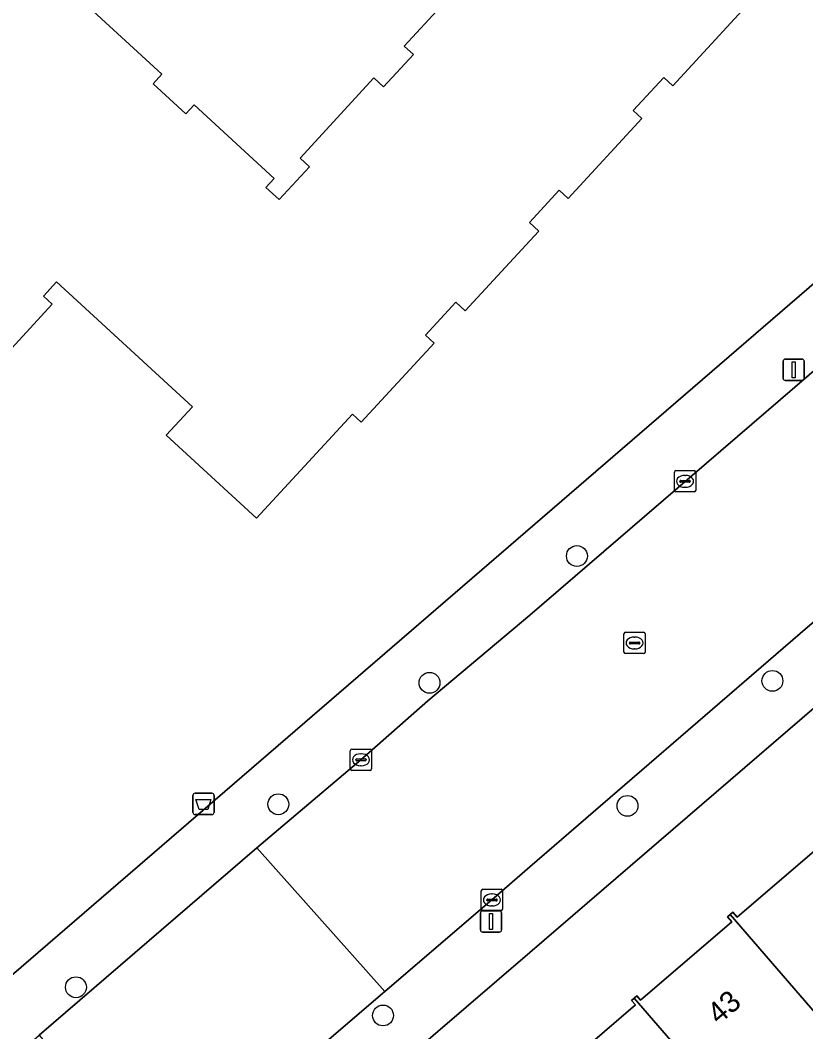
# Model space of a CAD drawing. Extents: x 159217 to 160349, y 381246 to 382172.
# Drawn here: x 159976.13 to 160012.93, y 381881.22 to 381928.65 of the extents above; entities that cross this region are included whole.
import ezdxf

# ---------------------------------------------------------------- set-up
doc = ezdxf.new("R2010")
doc.units = 0
for name, color, linetype in [('IMGEO_Afvalbak', 7, 'Continuous'), ('IMGEO_Boom', 7, 'Continuous'), ('IMGEO_Erf', 7, 'Continuous'), ('IMGEO_Kolk', 7, 'Continuous'), ('IMGEO_Lichtmast', 7, 'Continuous'), ('IMGEO_Pand', 7, 'Continuous'), ('IMGEO_Pand_nummerreeks', 7, 'Continuous'), ('IMGEO_Rijbaan_lokaal_open', 7, 'Continuous'), ('IMGEO_Rioolput', 7, 'Continuous'), ('IMGEO_Voetpad_open', 7, 'Continuous')]:
    doc.layers.add(name, color=color, linetype=linetype)

msp = doc.modelspace()

# ---------------------------------------------------------------- linework, layer by layer
at = {"layer": 'IMGEO_Afvalbak'}
for p, q in [((159984.22, 381891.506), (159984.22, 381892.306)), ((159984.22, 381892.306), (159984.22, 381891.506)), ((159984.32, 381892.406), (159985.11, 381892.406)), ((159985.11, 381892.406), (159984.32, 381892.406)), ((159985.21, 381892.306), (159985.21, 381891.506)), ((159985.21, 381891.506), (159985.21, 381892.306)), ((159985.11, 381891.406), (159984.32, 381891.406)), ((159984.32, 381891.406), (159985.11, 381891.406))]:
    msp.add_line(p, q, dxfattribs=at)
msp.add_lwpolyline([(159984.363, 381892.12), (159985.067, 381892.12), (159984.918, 381891.65), (159984.512, 381891.65), (159984.363, 381892.12)], dxfattribs=at)
for centre, start, end in [((159984.32, 381892.306), 90, 180), ((159984.32, 381892.306), 90, 180), ((159985.11, 381892.306), 0, 90), ((159985.11, 381892.306), 360, 90), ((159984.32, 381891.506), 180, 270), ((159984.32, 381891.506), 180, 270), ((159985.11, 381891.506), 270, 0), ((159985.11, 381891.506), 270, 0)]:
    msp.add_arc(centre, 0.1, start, end, dxfattribs=at)
at = {"layer": 'IMGEO_Boom'}
for centre in [(160002.212, 381903.529), (159995.305, 381897.584), (160011.37, 381897.674), (159988.223, 381891.889), (160004.58, 381891.813), (159978.741, 381883.309), (159993.128, 381881.988)]:
    msp.add_circle(centre, 0.489, dxfattribs=at)
at = {"layer": 'IMGEO_Erf'}
for points in [[(159951.731, 381863.172), (160032.516, 381932.902), (160035.937, 381935.855), (160047.054, 381945.45), (160050.259, 381948.217), (160066.708, 381962.801), (160069.798, 381966.001)], [(159978.979, 381929.596), (159982.763, 381926.114), (159982.355, 381925.672), (159983.882, 381924.266), (159984.273, 381924.691), (159988.028, 381921.236), (159987.637, 381920.812), (159988.261, 381920.238), (159989.682, 381921.781), (159989.241, 381922.186), (159992.7, 381925.946), (159993.152, 381925.53), (159994.549, 381927.047), (159994.122, 381927.441), (159997.583, 381931.202)], [(160010.143, 381929.312), (160006.704, 381925.575), (160006.278, 381925.966), (160004.848, 381924.412), (160005.258, 381924.036), (160001.807, 381920.286), (160001.38, 381920.679), (159999.988, 381919.167), (160000.422, 381918.767), (160000, 381918.308), (159996.978, 381915.024), (159996.539, 381915.428), (159995.118, 381913.884), (159995.52, 381913.515), (159992.106, 381909.805), (159991.69, 381910.187), (159987.202, 381905.31), (159982.975, 381909.2), (159984.197, 381910.527), (159977.837, 381916.38), (159977.219, 381915.709), (159977.626, 381915.335), (159974.164, 381911.574)], [(160033.475, 381913.761), (160000, 381884.944), (159992.495, 381878.483)], [(160000.606, 381878.737), (160004.954, 381882.478), (160004.766, 381882.696), (160004.889, 381882.802), (160005.012, 381882.908), (160005.191, 381882.7), (160009.466, 381886.38), (160009.266, 381886.612), (160009.392, 381886.721), (160009.521, 381886.832), (160009.726, 381886.595), (160013.99, 381890.266)]]:
    msp.add_lwpolyline(points, dxfattribs=at)
at = {"layer": 'IMGEO_Kolk'}
for p, q in [((160006.778, 381906.606), (160006.778, 381907.458)), ((160006.853, 381907.532), (160007.705, 381907.532)), ((160007.779, 381907.458), (160007.779, 381906.606)), ((160007.037, 381907.026), (160007.037, 381907.038)), ((160007.475, 381906.989), (160007.077, 381906.989)), ((160007.08, 381907.075), (160007.478, 381907.075)), ((160007.266, 381907.312), (160007.291, 381907.312)), ((160007.521, 381907.038), (160007.521, 381907.026)), ((160007.705, 381906.532), (160006.853, 381906.532)), ((160007.289, 381906.752), (160007.264, 381906.752)), ((159991.593, 381893.549), (159991.593, 381894.401)), ((159991.668, 381894.475), (159992.52, 381894.475)), ((159992.081, 381894.255), (159992.106, 381894.255)), ((159992.594, 381894.401), (159992.594, 381893.549)), ((159991.852, 381893.969), (159991.852, 381893.981)), ((159992.29, 381893.932), (159991.892, 381893.932)), ((159991.895, 381894.018), (159992.293, 381894.018)), ((159992.104, 381893.695), (159992.079, 381893.695)), ((159992.336, 381893.981), (159992.336, 381893.969)), ((159992.52, 381893.475), (159991.668, 381893.475)), ((159997.804, 381887.903), (159998.656, 381887.903)), ((159997.729, 381886.977), (159997.729, 381887.829)), ((159997.988, 381887.397), (159997.988, 381887.409)), ((159998.031, 381887.446), (159998.429, 381887.446)), ((159998.217, 381887.683), (159998.242, 381887.683)), ((159998.472, 381887.409), (159998.472, 381887.397)), ((159998.73, 381887.829), (159998.73, 381886.977)), ((159998.426, 381887.36), (159998.028, 381887.36)), ((159998.24, 381887.123), (159998.215, 381887.123)), ((159998.656, 381886.903), (159997.804, 381886.903))]:
    msp.add_line(p, q, dxfattribs=at)
for points in [[(160006.778, 381906.606), (160006.778, 381907.458)], [(160006.853, 381907.532), (160007.705, 381907.532)], [(160007.779, 381907.458), (160007.779, 381906.606)], [(160007.705, 381906.532), (160006.853, 381906.532)], [(159991.593, 381893.549), (159991.593, 381894.401)], [(159991.668, 381894.475), (159992.52, 381894.475)], [(159992.594, 381894.401), (159992.594, 381893.549)], [(159992.52, 381893.475), (159991.668, 381893.475)], [(159997.804, 381887.903), (159998.656, 381887.903)], [(159997.729, 381886.977), (159997.729, 381887.829)], [(159998.73, 381887.829), (159998.73, 381886.977)], [(159998.656, 381886.903), (159997.804, 381886.903)]]:
    msp.add_lwpolyline(points, dxfattribs=at)
for centre, radius, start, end in [((160006.855, 381907.456), 0.0765, 91.552, 178.448), ((160006.855, 381907.456), 0.0765, 91.552, 178.448), ((160007.703, 381907.456), 0.0765, 1.552, 88.448), ((160007.703, 381907.456), 0.0765, 1.552, 88.448), ((160007.077, 381907.035), 0.0403, 85.8775, 175.7526), ((160007.074, 381907.025), 0.0366, 178.938, 274.7102), ((160007.478, 381907.032), 0.043, 264.8664, 352.4533), ((160007.482, 381907.037), 0.0386, 1.7309, 96.639), ((160006.855, 381906.608), 0.0765, 181.552, 268.448), ((160006.855, 381906.608), 0.0765, 181.552, 268.448), ((160007.703, 381906.608), 0.0765, 271.552, 358.448), ((160007.703, 381906.608), 0.0765, 271.552, 358.448), ((159991.67, 381894.399), 0.0765, 91.552, 178.448), ((159991.67, 381894.399), 0.0765, 91.552, 178.448), ((159992.518, 381894.399), 0.0765, 1.552, 88.448), ((159992.518, 381894.399), 0.0765, 1.552, 88.448), ((159991.892, 381893.978), 0.0403, 85.8775, 175.7526), ((159991.889, 381893.968), 0.0366, 178.938, 274.7102), ((159992.293, 381893.975), 0.043, 264.8664, 352.4533), ((159992.297, 381893.98), 0.0386, 1.7309, 96.639), ((159991.67, 381893.551), 0.0765, 181.552, 268.448), ((159991.67, 381893.551), 0.0765, 181.552, 268.448), ((159992.518, 381893.551), 0.0765, 271.552, 358.448), ((159992.518, 381893.551), 0.0765, 271.552, 358.448), ((159997.806, 381887.827), 0.0765, 91.552, 178.448), ((159997.806, 381887.827), 0.0765, 91.552, 178.448), ((159998.654, 381887.827), 0.0765, 1.552, 88.448), ((159998.654, 381887.827), 0.0765, 1.552, 88.448), ((159998.028, 381887.406), 0.0403, 85.8775, 175.7526), ((159998.433, 381887.408), 0.0386, 1.7309, 96.639), ((159997.806, 381886.979), 0.0765, 181.552, 268.448), ((159997.806, 381886.979), 0.0765, 181.552, 268.448), ((159998.025, 381887.396), 0.0366, 178.938, 274.7102), ((159998.429, 381887.403), 0.043, 264.8664, 352.4533), ((159998.654, 381886.979), 0.0765, 271.552, 358.448), ((159998.654, 381886.979), 0.0765, 271.552, 358.448)]:
    msp.add_arc(centre, radius, start, end, dxfattribs=at)
for centre, major_axis, ratio, start_param, end_param in [((160007.265, 381907.032), (-0.387, 0.002), 0.722429, 4.712389, 7.853982), ((160007.29, 381907.032), (-0.39, 0.002), 0.717154, 1.570796, 4.712389), ((159992.08, 381893.975), (-0.387, 0.002), 0.722429, 4.712389, 7.853982), ((159992.105, 381893.975), (-0.39, 0.002), 0.717154, 1.570796, 4.712389), ((159998.216, 381887.403), (-0.387, 0.002), 0.722429, 4.712389, 7.853982), ((159998.241, 381887.403), (-0.39, 0.002), 0.717154, 1.570796, 4.712389)]:
    msp.add_ellipse(centre, major_axis=major_axis, ratio=ratio, start_param=start_param, end_param=end_param, dxfattribs=at)
at = {"layer": 'IMGEO_Lichtmast'}
for p, q in [((160011.872, 381911.859), (160011.872, 381912.659)), ((160011.872, 381912.659), (160011.872, 381911.859)), ((160011.972, 381912.759), (160012.762, 381912.759)), ((160012.762, 381912.759), (160011.972, 381912.759)), ((160012.862, 381912.659), (160012.862, 381911.859)), ((160012.862, 381911.859), (160012.862, 381912.659)), ((160012.762, 381911.759), (160011.972, 381911.759)), ((160011.972, 381911.759), (160012.762, 381911.759)), ((159997.693, 381885.999), (159997.693, 381886.799)), ((159997.693, 381886.799), (159997.693, 381885.999)), ((159997.793, 381886.899), (159998.583, 381886.899)), ((159998.583, 381886.899), (159997.793, 381886.899)), ((159998.683, 381886.799), (159998.683, 381885.999)), ((159998.683, 381885.999), (159998.683, 381886.799)), ((159998.583, 381885.899), (159997.793, 381885.899)), ((159997.793, 381885.899), (159998.583, 381885.899))]:
    msp.add_line(p, q, dxfattribs=at)
for points in [[(160012.292, 381912.634), (160012.442, 381912.634), (160012.442, 381911.884), (160012.292, 381911.884), (160012.292, 381912.634)], [(159998.113, 381886.774), (159998.263, 381886.774), (159998.263, 381886.024), (159998.113, 381886.024), (159998.113, 381886.774)]]:
    msp.add_lwpolyline(points, dxfattribs=at)
for centre, start, end in [((160011.972, 381912.659), 90, 180), ((160011.972, 381912.659), 90, 180), ((160012.762, 381912.659), 0, 90), ((160012.762, 381912.659), 360, 90), ((160011.972, 381911.859), 180, 270), ((160011.972, 381911.859), 180, 270), ((160012.762, 381911.859), 270, 0), ((160012.762, 381911.859), 270, 0), ((159997.793, 381886.799), 90, 180), ((159997.793, 381886.799), 90, 180), ((159998.583, 381886.799), 0, 90), ((159998.583, 381886.799), 360, 90), ((159997.793, 381885.999), 180, 270), ((159997.793, 381885.999), 180, 270), ((159998.583, 381885.999), 270, 0), ((159998.583, 381885.999), 270, 0)]:
    msp.add_arc(centre, 0.1, start, end, dxfattribs=at)
at = {"layer": 'IMGEO_Pand'}
for points in [[(159997.583, 381931.202), (159994.122, 381927.441), (159994.549, 381927.047), (159993.152, 381925.53), (159992.7, 381925.946), (159989.241, 381922.186), (159989.682, 381921.781), (159988.261, 381920.238), (159987.637, 381920.812), (159988.028, 381921.236), (159984.273, 381924.691), (159983.882, 381924.266), (159982.355, 381925.672), (159982.763, 381926.114), (159978.979, 381929.596)], [(159974.164, 381911.574), (159977.626, 381915.335), (159977.219, 381915.709), (159977.837, 381916.38), (159984.197, 381910.527), (159982.975, 381909.2), (159987.202, 381905.31), (159991.69, 381910.187), (159992.106, 381909.805), (159995.52, 381913.515), (159995.118, 381913.884), (159996.539, 381915.428), (159996.978, 381915.024), (160000, 381918.308), (160000.422, 381918.767), (159999.988, 381919.167), (160001.38, 381920.679), (160001.807, 381920.286), (160005.258, 381924.036), (160004.848, 381924.412), (160006.278, 381925.966), (160006.704, 381925.575), (160010.143, 381929.312)]]:
    msp.add_lwpolyline(points, dxfattribs=at)
for points in [[(160013.927, 381890.622), (160013.787, 381890.502), (160013.99, 381890.266), (160009.726, 381886.595), (160009.521, 381886.832), (160009.392, 381886.721), (160014.863, 381880.397), (160019.398, 381884.3)], [(160010.339, 381876.502), (160014.863, 381880.397), (160009.392, 381886.721), (160009.266, 381886.612), (160009.466, 381886.38), (160005.191, 381882.7), (160005.012, 381882.908), (160004.889, 381882.802)], [(160005.743, 381872.547), (160010.339, 381876.502), (160004.889, 381882.802), (160004.766, 381882.696), (160004.954, 381882.478), (160000.606, 381878.737), (160000.413, 381878.962), (160000.287, 381878.853)]]:
    msp.add_lwpolyline(points, close=True, dxfattribs=at)
at = {"layer": 'IMGEO_Rijbaan_lokaal_open'}
msp.add_lwpolyline([(160059.423, 381951.93), (160052.575, 381946.033), (160049.17, 381943.102), (160037.988, 381933.472), (160034.563, 381930.523), (160000, 381900.762), (159995.231, 381896.742), (159992.095, 381893.974), (159987.216, 381889.848), (159993.21, 381883.114), (159998.229, 381887.404), (160000, 381888.954), (160012.675, 381899.899), (160065.438, 381945.337)], dxfattribs=at)
msp.add_lwpolyline([(159993.21, 381883.114), (159987.216, 381889.848), (159977.026, 381881.069), (159982.838, 381874.211)], close=True, dxfattribs=at)
at = {"layer": 'IMGEO_Rioolput'}
for p, q in [((160004.411, 381899.026), (160004.411, 381899.878)), ((160004.486, 381899.952), (160005.338, 381899.952)), ((160005.412, 381899.878), (160005.412, 381899.026)), ((160004.67, 381899.446), (160004.67, 381899.458)), ((160005.108, 381899.409), (160004.71, 381899.409)), ((160004.713, 381899.495), (160005.111, 381899.495)), ((160004.899, 381899.732), (160004.924, 381899.732)), ((160005.154, 381899.458), (160005.154, 381899.446)), ((160005.338, 381898.952), (160004.486, 381898.952)), ((160004.922, 381899.172), (160004.897, 381899.172))]:
    msp.add_line(p, q, dxfattribs=at)
for points in [[(160004.411, 381899.026), (160004.411, 381899.878)], [(160004.486, 381899.952), (160005.338, 381899.952)], [(160005.412, 381899.878), (160005.412, 381899.026)], [(160005.338, 381898.952), (160004.486, 381898.952)]]:
    msp.add_lwpolyline(points, dxfattribs=at)
for centre, radius, start, end in [((160004.488, 381899.876), 0.0765, 91.552, 178.448), ((160004.488, 381899.876), 0.0765, 91.552, 178.448), ((160005.336, 381899.876), 0.0765, 1.552, 88.448), ((160005.336, 381899.876), 0.0765, 1.552, 88.448), ((160004.71, 381899.455), 0.0403, 85.8775, 175.7526), ((160004.707, 381899.445), 0.0366, 178.938, 274.7102), ((160005.111, 381899.452), 0.043, 264.8664, 352.4533), ((160005.115, 381899.457), 0.0386, 1.7309, 96.639), ((160004.488, 381899.028), 0.0765, 181.552, 268.448), ((160004.488, 381899.028), 0.0765, 181.552, 268.448), ((160005.336, 381899.028), 0.0765, 271.552, 358.448), ((160005.336, 381899.028), 0.0765, 271.552, 358.448)]:
    msp.add_arc(centre, radius, start, end, dxfattribs=at)
for centre, major_axis, ratio, start_param, end_param in [((160004.898, 381899.452), (-0.387, 0.002), 0.722429, 4.712389, 7.853982), ((160004.923, 381899.452), (-0.39, 0.002), 0.717154, 1.570796, 4.712389)]:
    msp.add_ellipse(centre, major_axis=major_axis, ratio=ratio, start_param=start_param, end_param=end_param, dxfattribs=at)
at = {"layer": 'IMGEO_Voetpad_open'}
for points in [[(160076.575, 381973.183), (160073.471, 381969.337), (160070.179, 381965.651), (160069.798, 381966.001), (160066.708, 381962.801), (160050.259, 381948.217), (160047.054, 381945.45), (160035.937, 381935.855), (160032.516, 381932.902), (159951.731, 381863.172), (159947.76, 381859.745), (159941.192, 381854.075), (159940.376, 381853.371), (159939.046, 381852.174)], [(159992.095, 381893.974), (159995.231, 381896.742), (160000, 381900.762), (160034.563, 381930.523), (160037.988, 381933.472), (160049.17, 381943.102), (160052.575, 381946.033), (160059.423, 381951.93), (160061.392, 381953.701), (160066.142, 381958.062), (160068.368, 381960.235), (160072.029, 381964.202), (160072.21, 381964.39), (160072.959, 381965.169), (160073.897, 381966.186)], [(160065.438, 381945.337), (160012.675, 381899.899), (160000, 381888.954), (159998.229, 381887.404), (159993.21, 381883.114), (159982.838, 381874.211), (159972.211, 381865.09), (159952.156, 381847.982), (159950.972, 381846.948)], [(159948.828, 381842.865), (159948.378, 381831.596), (159952.057, 381829.709), (159957.077, 381834.899), (159958.818, 381836.919), (159955.642, 381840.217), (159957.007, 381841.635), (159990.64, 381876.569), (159990.482, 381876.75), (159992.495, 381878.483), (160000, 381884.944), (160033.475, 381913.761), (160034.634, 381914.758), (160067.439, 381942.998)], [(159945.204, 381853.564), (159946.153, 381854.406), (159947.613, 381855.663), (159949.004, 381856.893), (159950.517, 381858.23), (159954.349, 381861.525), (159971.031, 381875.869), (159976.51, 381880.603), (159977.026, 381881.069), (159987.216, 381889.848), (159992.095, 381893.974)]]:
    msp.add_lwpolyline(points, dxfattribs=at)

# ---------------------------------------------------------------- texts
at = {"layer": 'IMGEO_Pand_nummerreeks'}
msp.add_text('43', height=1, rotation=40.7999, dxfattribs=at).set_placement((160008.856, 381881.525))

doc.saveas('drawing.dxf')
